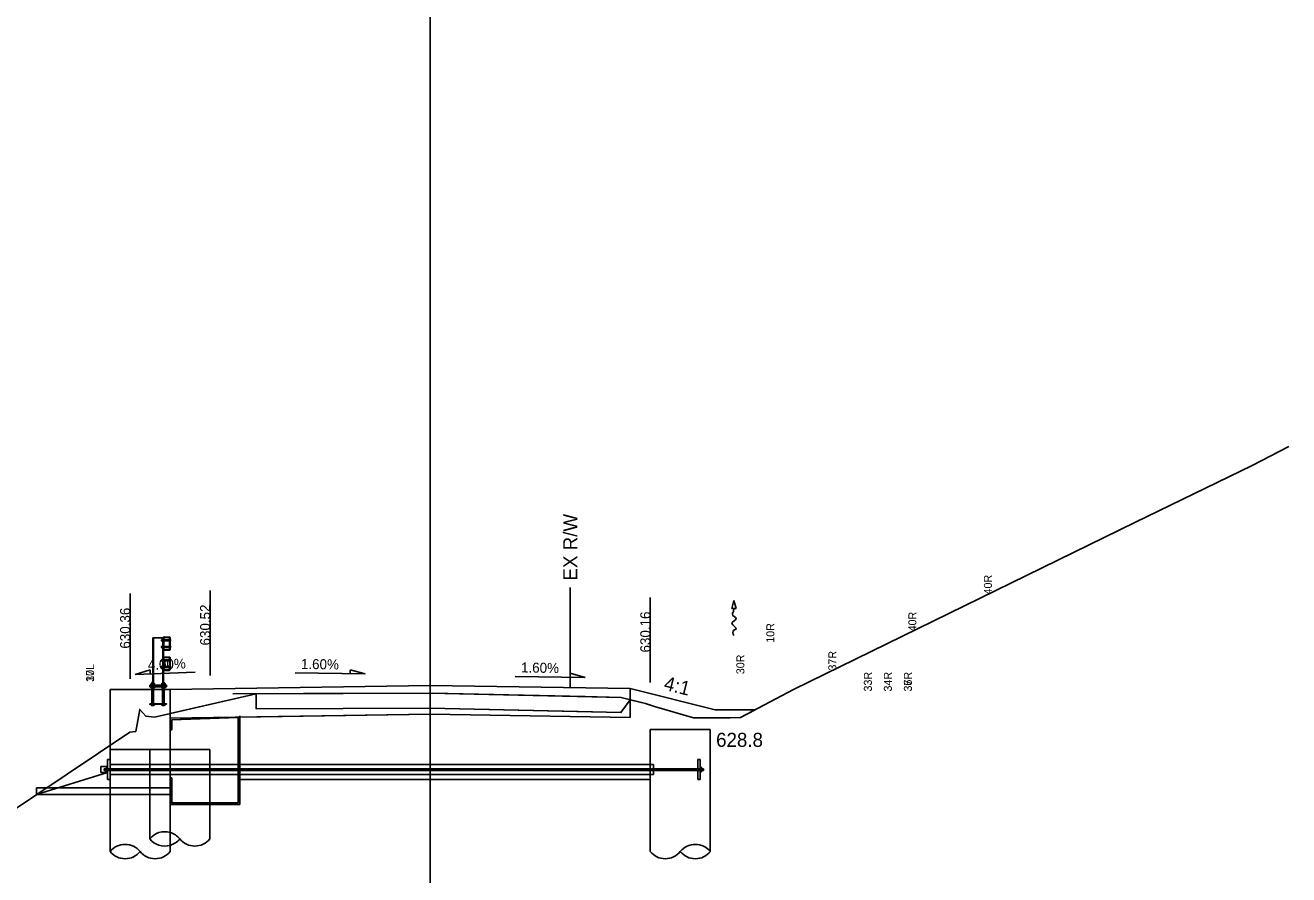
# Model space of a CAD drawing. Extents: x 1866342 to 1870084, y 421982 to 426629.
# Drawn here: x 1866447.9 to 1866511, y 425518.2 to 425560.6 of the extents above; entities that cross this region are included whole.
import ezdxf

# ---------------------------------------------------------------- set-up
doc = ezdxf.new("R2010")
doc.units = 0
for name, color, linetype in [('BR_P_Det_Object', 7, 'Continuous'), ('BR_P_Drain_Object', 7, 'Continuous'), ('BR_P_Gen_Hatch', 7, 'Continuous'), ('BR_P_Gen_Porous_Backfill', 7, 'Continuous'), ('BR_P_Sub_Deep_Hidden', 7, 'Continuous'), ('BR_P_Sub_Deep_Object', 7, 'Continuous'), ('BR_P_Sub_Object', 7, 'Continuous'), ('DR_P_Flow_Arrow', 7, 'Continuous'), ('GK_Cells', 7, 'Continuous'), ('RW_X_Fee_RW', 7, 'Continuous'), ('ST_Details', 7, 'Continuous'), ('XS_P_Annotation', 7, 'Continuous'), ('XS_P_Earthwork_Shapes', 7, 'Continuous'), ('XS_P_Finished_Grade', 7, 'Continuous'), ('XS_P_Pavt_Surface', 7, 'Continuous'), ('XS_P_Subgrade', 7, 'Continuous'), ('XS_P_Text_Info', 7, 'Continuous'), ('XS_P_Text_MarkedPoint', 7, 'Continuous'), ('XS_X_Ground_Line', 7, 'Continuous')]:
    doc.layers.add(name, color=color, linetype=linetype)

msp = doc.modelspace()

# ---------------------------------------------------------------- linework, layer by layer
at = {"layer": 'BR_P_Det_Object'}
for p, q in [((1866451.994, 425522.946), (1866451.994, 425523.946)), ((1866451.994, 425523.946), (1866452.119, 425523.946)), ((1866452.119, 425523.946), (1866452.119, 425522.946)), ((1866481.494, 425523.946), (1866481.494, 425522.946)), ((1866481.619, 425523.946), (1866481.494, 425523.946)), ((1866481.619, 425522.946), (1866481.619, 425523.946)), ((1866451.66, 425523.296), (1866451.66, 425523.594)), ((1866451.66, 425523.594), (1866451.994, 425523.594)), ((1866451.994, 425523.296), (1866451.66, 425523.296)), ((1866451.827, 425523.488), (1866481.785, 425523.488)), ((1866451.827, 425523.405), (1866451.827, 425523.488)), ((1866451.827, 425523.405), (1866481.785, 425523.405)), ((1866451.994, 425523.541), (1866451.93, 425523.541)), ((1866451.93, 425523.352), (1866451.93, 425523.541)), ((1866451.994, 425523.352), (1866451.93, 425523.352)), ((1866452.119, 425523.696), (1866455.119, 425523.696)), ((1866452.119, 425523.196), (1866455.119, 425523.196)), ((1866481.619, 425523.561), (1866481.682, 425523.561)), ((1866481.619, 425523.331), (1866481.682, 425523.331)), ((1866481.682, 425523.331), (1866481.682, 425523.561)), ((1866481.785, 425523.405), (1866481.785, 425523.488)), ((1866452.119, 425522.946), (1866451.994, 425522.946)), ((1866481.619, 425522.946), (1866481.494, 425522.946))]:
    msp.add_line(p, q, dxfattribs=at)
at = {"layer": 'BR_P_Drain_Object'}
for p, q in [((1866455.119, 425523.696), (1866479.285, 425523.696)), ((1866455.119, 425523.196), (1866479.285, 425523.196)), ((1866479.285, 425523.696), (1866479.285, 425523.196)), ((1866448.434, 425522.53), (1866455.119, 425522.53)), ((1866448.434, 425522.196), (1866448.434, 425522.53)), ((1866448.434, 425522.196), (1866455.119, 425522.196))]:
    msp.add_line(p, q, dxfattribs=at)
at = {"layer": 'BR_P_Gen_Hatch'}
msp.add_lwpolyline([(1866455.119, 425525.429), (1866455.202, 425525.429), (1866455.202, 425525.929), (1866458.519, 425526.052), (1866458.519, 425521.78), (1866455.202, 425521.78), (1866455.202, 425523.03), (1866455.119, 425523.03)], close=True, dxfattribs=at)
at = {"layer": 'BR_P_Gen_Porous_Backfill'}
for p, q in [((1866455.202, 425525.929), (1866458.119, 425526.046)), ((1866455.202, 425525.429), (1866455.202, 425525.929)), ((1866458.519, 425526.052), (1866458.119, 425526.046)), ((1866458.519, 425521.78), (1866458.519, 425526.052)), ((1866455.202, 425525.429), (1866455.119, 425525.429)), ((1866455.202, 425523.03), (1866455.119, 425523.03)), ((1866455.202, 425521.78), (1866455.202, 425523.03)), ((1866455.202, 425521.78), (1866458.519, 425521.78))]:
    msp.add_line(p, q, dxfattribs=at)
at = {"layer": 'BR_P_Sub_Deep_Hidden'}
msp.add_line((1866457.103, 425524.446), (1866455.119, 425524.446), dxfattribs=at)
for points in [[(1866454.103, 425519.983), (1866454.103, 425524.446)], [(1866457.103, 425521.696), (1866457.103, 425524.446)]]:
    msp.add_lwpolyline(points, dxfattribs=at)
for centre, major_axis, start_param, end_param in [((1866454.853, 425519.38), (0.908, 0.32), 0.952163, 2.125879), ((1866454.853, 425520.586), (0.908, -0.32), 4.157306, 5.331022)]:
    msp.add_ellipse(centre, major_axis=major_axis, ratio=0.999997, start_param=start_param, end_param=end_param, dxfattribs=at)
at = {"layer": 'BR_P_Sub_Deep_Object'}
msp.add_line((1866479.119, 425525.446), (1866482.119, 425525.446), dxfattribs=at)
for points in [[(1866479.119, 425519.35), (1866479.119, 425525.446)], [(1866482.119, 425519.35), (1866482.119, 425525.446)], [(1866452.119, 425519.35), (1866452.119, 425524.446)], [(1866455.119, 425519.35), (1866455.119, 425524.446)], [(1866457.103, 425519.983), (1866457.103, 425521.696)]]:
    msp.add_lwpolyline(points, dxfattribs=at)
for centre, major_axis, start_param, end_param in [((1866454.853, 425519.38), (0.908, 0.32), 0.338571, 0.952163), ((1866452.869, 425518.747), (0.908, 0.32), 0.338571, 2.125879), ((1866454.853, 425520.586), (0.908, -0.32), 5.331022, 5.944615), ((1866456.353, 425520.586), (0.908, 0.32), 3.480163, 5.267472), ((1866481.369, 425518.747), (-0.908, 0.32), 4.157306, 5.944615), ((1866452.869, 425519.953), (0.908, -0.32), 4.157306, 5.944615), ((1866454.369, 425519.953), (0.908, 0.32), 3.480163, 5.267472), ((1866479.869, 425519.953), (-0.908, 0.32), 1.015713, 2.803022), ((1866481.369, 425519.953), (-0.908, -0.32), 0.33857, 2.125879)]:
    msp.add_ellipse(centre, major_axis=major_axis, ratio=0.999997, start_param=start_param, end_param=end_param, dxfattribs=at)
at = {"layer": 'BR_P_Sub_Object'}
for p, q in [((1866455.119, 425527.446), (1866452.119, 425527.446)), ((1866452.119, 425527.446), (1866452.119, 425524.446)), ((1866455.119, 425524.446), (1866455.119, 425527.446))]:
    msp.add_line(p, q, dxfattribs=at)
msp.add_lwpolyline([(1866455.119, 425524.446), (1866452.119, 425524.446)], dxfattribs=at)
at = {"layer": 'DR_P_Flow_Arrow'}
for p, q in [((1866483.188, 425531.488), (1866483.295, 425531.888)), ((1866483.402, 425531.488), (1866483.188, 425531.488)), ((1866483.295, 425531.888), (1866483.402, 425531.488))]:
    msp.add_line(p, q, dxfattribs=at)
msp.add_spline([(1866483.294, 425531.489), (1866483.294, 425531.473), (1866483.256, 425531.308), (1866483.22, 425531.204), (1866483.404, 425530.992), (1866483.198, 425530.75), (1866483.404, 425530.47), (1866483.292, 425530.413), (1866483.295, 425530.138)], degree=3, dxfattribs=at)
at = {"layer": 'GK_Cells'}
msp.add_line((1866468.119, 425490.634), (1866468.119, 425637.486), dxfattribs=at)
at = {"layer": 'RW_X_Fee_RW'}
msp.add_line((1866475.119, 425527.542), (1866475.119, 425532.542), dxfattribs=at)
at = {"layer": 'ST_Details'}
for p, q in [((1866454.254, 425530.03), (1866454.254, 425527.811)), ((1866454.785, 425530.03), (1866454.254, 425530.03)), ((1866454.292, 425530.03), (1866454.292, 425527.805)), ((1866454.701, 425529.931), (1866454.685, 425529.931)), ((1866454.685, 425529.931), (1866454.685, 425529.879)), ((1866454.701, 425529.879), (1866454.685, 425529.879)), ((1866454.701, 425529.597), (1866454.685, 425529.597)), ((1866454.685, 425529.597), (1866454.685, 425529.545)), ((1866454.701, 425529.545), (1866454.685, 425529.545)), ((1866454.701, 425529.938), (1866454.701, 425529.871)), ((1866454.701, 425529.605), (1866454.701, 425529.538)), ((1866454.71, 425529.883), (1866454.747, 425529.883)), ((1866454.71, 425529.549), (1866454.747, 425529.549)), ((1866454.747, 425529.949), (1866454.711, 425529.949)), ((1866454.711, 425529.927), (1866454.747, 425529.927)), ((1866454.711, 425529.86), (1866454.747, 425529.86)), ((1866454.747, 425529.616), (1866454.711, 425529.616)), ((1866454.711, 425529.593), (1866454.747, 425529.593)), ((1866454.711, 425529.527), (1866454.747, 425529.527)), ((1866454.747, 425530.03), (1866454.747, 425527.805)), ((1866454.747, 425529.86), (1866454.747, 425529.949)), ((1866454.747, 425529.527), (1866454.747, 425529.616)), ((1866454.785, 425530.03), (1866454.785, 425527.811)), ((1866454.785, 425530.019), (1866454.785, 425529.457)), ((1866454.811, 425530.019), (1866454.811, 425529.457)), ((1866454.811, 425529.931), (1866455.093, 425529.931)), ((1866454.811, 425529.879), (1866455.093, 425529.879)), ((1866454.811, 425529.597), (1866455.093, 425529.597)), ((1866454.811, 425529.545), (1866455.093, 425529.545)), ((1866455.067, 425530.071), (1866454.837, 425530.071)), ((1866455.067, 425530.045), (1866454.837, 425530.045)), ((1866455.093, 425529.457), (1866455.093, 425530.019)), ((1866455.119, 425529.457), (1866455.119, 425530.019)), ((1866454.701, 425528.931), (1866454.685, 425528.931)), ((1866454.685, 425528.931), (1866454.685, 425528.879)), ((1866454.701, 425528.879), (1866454.685, 425528.879)), ((1866454.701, 425528.938), (1866454.701, 425528.871)), ((1866454.71, 425528.883), (1866454.747, 425528.883)), ((1866454.747, 425528.949), (1866454.711, 425528.949)), ((1866454.711, 425528.927), (1866454.747, 425528.927)), ((1866454.711, 425528.86), (1866454.747, 425528.86)), ((1866454.747, 425528.86), (1866454.747, 425528.949)), ((1866454.785, 425529.04), (1866454.785, 425528.436)), ((1866454.811, 425529.019), (1866454.811, 425528.457)), ((1866454.811, 425528.931), (1866455.093, 425528.931)), ((1866454.811, 425528.879), (1866455.093, 425528.879)), ((1866455.087, 425529.071), (1866454.817, 425529.071)), ((1866454.837, 425529.431), (1866455.067, 425529.431)), ((1866454.837, 425529.405), (1866455.067, 425529.405)), ((1866455.067, 425529.045), (1866454.837, 425529.045)), ((1866455.093, 425528.457), (1866455.093, 425529.019)), ((1866455.119, 425528.436), (1866455.119, 425529.04)), ((1866454.701, 425528.597), (1866454.685, 425528.597)), ((1866454.685, 425528.597), (1866454.685, 425528.545)), ((1866454.701, 425528.545), (1866454.685, 425528.545)), ((1866454.701, 425528.605), (1866454.701, 425528.538)), ((1866454.71, 425528.549), (1866454.747, 425528.549)), ((1866454.747, 425528.616), (1866454.711, 425528.616)), ((1866454.711, 425528.593), (1866454.747, 425528.593)), ((1866454.711, 425528.527), (1866454.747, 425528.527)), ((1866454.747, 425528.527), (1866454.747, 425528.616)), ((1866454.811, 425528.597), (1866455.093, 425528.597)), ((1866454.811, 425528.545), (1866455.093, 425528.545)), ((1866454.817, 425528.405), (1866455.087, 425528.405)), ((1866454.837, 425528.431), (1866455.067, 425528.431)), ((1866454.171, 425527.68), (1866454.337, 425527.68)), ((1866454.171, 425527.665), (1866454.171, 425527.68)), ((1866454.337, 425527.665), (1866454.171, 425527.665)), ((1866454.176, 425527.746), (1866454.176, 425527.68)), ((1866454.332, 425527.68), (1866454.176, 425527.68)), ((1866454.195, 425527.762), (1866454.312, 425527.762)), ((1866454.212, 425527.801), (1866454.223, 425527.811)), ((1866454.212, 425527.801), (1866454.296, 425527.801)), ((1866454.212, 425527.801), (1866454.212, 425527.762)), ((1866454.212, 425527.79), (1866454.296, 425527.79)), ((1866454.212, 425527.78), (1866454.296, 425527.78)), ((1866454.212, 425527.77), (1866454.296, 425527.77)), ((1866454.212, 425527.665), (1866454.212, 425527.582)), ((1866454.215, 425527.746), (1866454.215, 425527.68)), ((1866454.285, 425527.811), (1866454.223, 425527.811)), ((1866454.285, 425527.811), (1866454.296, 425527.801)), ((1866454.293, 425527.746), (1866454.293, 425527.68)), ((1866454.296, 425527.762), (1866454.296, 425527.801)), ((1866454.296, 425527.582), (1866454.296, 425527.665)), ((1866454.332, 425527.746), (1866454.332, 425527.68)), ((1866454.337, 425527.68), (1866454.337, 425527.665)), ((1866454.868, 425527.68), (1866454.702, 425527.68)), ((1866454.702, 425527.68), (1866454.702, 425527.665)), ((1866454.702, 425527.665), (1866454.868, 425527.665)), ((1866454.707, 425527.746), (1866454.707, 425527.68)), ((1866454.707, 425527.68), (1866454.863, 425527.68)), ((1866454.844, 425527.762), (1866454.726, 425527.762)), ((1866454.754, 425527.811), (1866454.743, 425527.801)), ((1866454.827, 425527.801), (1866454.743, 425527.801)), ((1866454.743, 425527.762), (1866454.743, 425527.801)), ((1866454.827, 425527.79), (1866454.743, 425527.79)), ((1866454.827, 425527.78), (1866454.743, 425527.78)), ((1866454.827, 425527.77), (1866454.743, 425527.77)), ((1866454.743, 425527.582), (1866454.743, 425527.665)), ((1866454.746, 425527.746), (1866454.746, 425527.68)), ((1866454.754, 425527.811), (1866454.816, 425527.811)), ((1866454.827, 425527.801), (1866454.816, 425527.811)), ((1866454.824, 425527.746), (1866454.824, 425527.68)), ((1866454.827, 425527.801), (1866454.827, 425527.762)), ((1866454.827, 425527.665), (1866454.827, 425527.582)), ((1866454.863, 425527.746), (1866454.863, 425527.68)), ((1866454.868, 425527.665), (1866454.868, 425527.68)), ((1866454.171, 425527.582), (1866454.337, 425527.582)), ((1866454.171, 425527.567), (1866454.171, 425527.582)), ((1866454.337, 425527.567), (1866454.171, 425527.567)), ((1866454.176, 425527.537), (1866454.176, 425527.567)), ((1866454.195, 425527.522), (1866454.312, 425527.522)), ((1866454.212, 425527.457), (1866454.212, 425527.522)), ((1866454.212, 425527.457), (1866454.212, 425526.738)), ((1866454.215, 425527.537), (1866454.215, 425527.567)), ((1866454.293, 425527.537), (1866454.293, 425527.567)), ((1866454.296, 425527.457), (1866454.296, 425527.522)), ((1866454.296, 425526.738), (1866454.296, 425527.457)), ((1866454.332, 425527.537), (1866454.332, 425527.567)), ((1866454.337, 425527.582), (1866454.337, 425527.567)), ((1866454.702, 425527.582), (1866454.868, 425527.582)), ((1866454.702, 425527.567), (1866454.702, 425527.582)), ((1866454.868, 425527.567), (1866454.702, 425527.567)), ((1866454.707, 425527.537), (1866454.707, 425527.567)), ((1866454.726, 425527.522), (1866454.844, 425527.522)), ((1866454.743, 425527.457), (1866454.743, 425527.522)), ((1866454.743, 425526.738), (1866454.743, 425527.457)), ((1866454.746, 425527.537), (1866454.746, 425527.567)), ((1866454.824, 425527.537), (1866454.824, 425527.567)), ((1866454.827, 425527.457), (1866454.827, 425527.522)), ((1866454.827, 425527.457), (1866454.827, 425526.738)), ((1866454.863, 425527.537), (1866454.863, 425527.567)), ((1866454.868, 425527.582), (1866454.868, 425527.567)), ((1866454.176, 425526.672), (1866454.176, 425526.707)), ((1866454.195, 425526.656), (1866454.312, 425526.656)), ((1866454.215, 425526.672), (1866454.215, 425526.707)), ((1866454.293, 425526.672), (1866454.293, 425526.707)), ((1866454.332, 425526.672), (1866454.332, 425526.707)), ((1866454.707, 425526.672), (1866454.707, 425526.707)), ((1866454.844, 425526.656), (1866454.726, 425526.656)), ((1866454.746, 425526.672), (1866454.746, 425526.707)), ((1866454.824, 425526.672), (1866454.824, 425526.707)), ((1866454.863, 425526.672), (1866454.863, 425526.707))]:
    msp.add_line(p, q, dxfattribs=at)
for points in [[(1866454.103, 425527.665), (1866454.936, 425527.665), (1866454.936, 425527.582), (1866454.103, 425527.582)], [(1866454.103, 425526.738), (1866454.936, 425526.738), (1866454.936, 425526.707), (1866454.103, 425526.707)]]:
    msp.add_lwpolyline(points, close=True, dxfattribs=at)
for centre, radius, start, end in [((1866454.837, 425530.019), 0.0521, 90, 180), ((1866454.837, 425530.019), 0.026, 90, 180), ((1866455.067, 425530.019), 0.0521, 0, 90), ((1866455.067, 425530.019), 0.026, 0, 90), ((1866455.091, 425529.905), 0.0558, 300, 60), ((1866455.091, 425529.571), 0.0558, 300, 60), ((1866454.837, 425529.457), 0.0521, 180, 270), ((1866454.817, 425529.04), 0.0312, 90, 180), ((1866454.837, 425529.457), 0.026, 180, 270), ((1866454.837, 425529.019), 0.026, 90, 180), ((1866455.067, 425529.457), 0.0521, 270, 0), ((1866455.067, 425529.457), 0.026, 270, 0), ((1866455.067, 425529.019), 0.026, 0, 90), ((1866455.087, 425529.04), 0.0312, 0, 90), ((1866455.091, 425528.905), 0.0558, 300, 60), ((1866454.817, 425528.436), 0.0312, 180, 270), ((1866454.837, 425528.457), 0.026, 180, 270), ((1866455.067, 425528.457), 0.026, 270, 0), ((1866455.087, 425528.436), 0.0312, 270, 0), ((1866455.091, 425528.571), 0.0558, 300, 60)]:
    msp.add_arc(centre, radius, start, end, dxfattribs=at)
for centre, major_axis, ratio, start_param, end_param in [((1866454.711, 425529.938), (0, -0.0111), 0.939759, 3.141593, 6.283185), ((1866454.711, 425529.905), (0, -0.0222), 0.469173, 3.141593, 6.283185), ((1866454.711, 425529.871), (0, 0.0111), 0.939759, 0, 3.141593), ((1866454.711, 425529.605), (0, -0.0111), 0.939759, 3.141593, 6.283185), ((1866454.711, 425529.571), (0, -0.0222), 0.469173, 3.141593, 6.283185), ((1866454.711, 425529.538), (0, 0.0111), 0.939759, 0, 3.141593), ((1866454.711, 425528.938), (0, -0.0111), 0.939759, 3.141593, 6.283185), ((1866454.711, 425528.905), (0, -0.0222), 0.469173, 3.141593, 6.283185), ((1866454.711, 425528.871), (0, 0.0111), 0.939759, 0, 3.141593), ((1866454.711, 425528.605), (0, -0.0111), 0.939759, 3.141593, 6.283185), ((1866454.711, 425528.571), (0, -0.0222), 0.469173, 3.141593, 6.283185), ((1866454.711, 425528.538), (0, 0.0111), 0.939759, 0, 3.141593), ((1866454.195, 425527.746), (0.0195, 0), 0.798056, 0, 3.141593), ((1866454.254, 425527.746), (0.0391, 0), 0.399304, 0, 3.141593), ((1866454.312, 425527.746), (0.0195, 0), 0.798056, 0, 3.141593), ((1866454.726, 425527.746), (-0.0195, 0), 0.798056, 3.141593, 6.283185), ((1866454.785, 425527.746), (-0.0391, 0), 0.399304, 3.141593, 6.283185), ((1866454.844, 425527.746), (-0.0195, 0), 0.798056, 3.141593, 6.283185), ((1866454.195, 425527.537), (0.0195, 0), 0.798056, 3.141593, 6.283185), ((1866454.254, 425527.537), (0.0391, 0), 0.399304, 3.141593, 6.283185), ((1866454.312, 425527.537), (0.0195, 0), 0.798056, 3.141593, 6.283185), ((1866454.726, 425527.537), (0.0195, 0), 0.798056, 3.141593, 6.283185), ((1866454.785, 425527.537), (0.0391, 0), 0.399304, 3.141593, 6.283185), ((1866454.844, 425527.537), (0.0195, 0), 0.798056, 3.141593, 6.283185), ((1866454.195, 425526.672), (0.0195, 0), 0.798056, 3.141593, 6.283185), ((1866454.254, 425526.672), (0.0391, 0), 0.399304, 3.141593, 6.283185), ((1866454.312, 425526.672), (0.0195, 0), 0.798056, 3.141593, 6.283185), ((1866454.726, 425526.672), (-0.0195, 0), 0.798056, 0, 3.141593), ((1866454.785, 425526.672), (-0.0391, 0), 0.399304, 0, 3.141593), ((1866454.844, 425526.672), (-0.0195, 0), 0.798056, 0, 3.141593)]:
    msp.add_ellipse(centre, major_axis=major_axis, ratio=ratio, start_param=start_param, end_param=end_param, dxfattribs=at)
at = {"layer": 'XS_P_Annotation'}
for q in [(1866455.119, 425527.446), (1866478.119, 425527.494)]:
    msp.add_line((1866468.119, 425527.654), q, dxfattribs=at)
at = {"layer": 'XS_P_Earthwork_Shapes'}
for p, q in [((1866482.366, 425526.433), (1866478.119, 425527.494)), ((1866478.119, 425527.494), (1866478.119, 425526.934)), ((1866478.119, 425526.057), (1866478.119, 425526.934)), ((1866478.119, 425526.934), (1866478.879, 425526.743)), ((1866484.366, 425526.433), (1866482.366, 425526.433)), ((1866455.119, 425526.245), (1866455.119, 425526.009)), ((1866468.119, 425526.217), (1866478.119, 425526.057))]:
    msp.add_line(p, q, dxfattribs=at)
for points in [[(1866478.119, 425526.934), (1866477.648, 425526.298), (1866475.508, 425526.347), (1866468.119, 425526.517), (1866459.426, 425526.479), (1866459.422, 425527.229), (1866455.119, 425526.245)], [(1866459.422, 425527.229), (1866468.119, 425527.267), (1866477.666, 425527.048)], [(1866459.426, 425526.479), (1866468.112, 425526.517), (1866477.648, 425526.298)], [(1866478.879, 425526.743), (1866479.326, 425526.6), (1866481.28, 425526.037), (1866483.117, 425526.04), (1866483.635, 425526.045), (1866484.366, 425526.433)], [(1866455.119, 425526.009), (1866458.603, 425526.065), (1866468.119, 425526.217)]]:
    msp.add_lwpolyline(points, dxfattribs=at)
at = {"layer": 'XS_P_Finished_Grade'}
for p, q in [((1866478.119, 425527.494), (1866482.366, 425526.433)), ((1866482.366, 425526.433), (1866484.366, 425526.433)), ((1866451.994, 425523.294), (1866448.434, 425522.196))]:
    msp.add_line(p, q, dxfattribs=at)
at = {"layer": 'XS_P_Pavt_Surface'}
for p, q in [((1866458.254, 425527.224), (1866468.254, 425527.267)), ((1866468.254, 425527.267), (1866477.666, 425527.048))]:
    msp.add_line(p, q, dxfattribs=at)
at = {"layer": 'XS_P_Subgrade'}
for p, q in [((1866455.119, 425527.446), (1866455.119, 425526.009)), ((1866455.119, 425527.446), (1866455.119, 425526.009)), ((1866478.119, 425527.494), (1866478.119, 425526.057)), ((1866468.119, 425526.217), (1866455.119, 425526.009)), ((1866458.603, 425521.696), (1866458.603, 425526.129)), ((1866468.119, 425526.217), (1866478.119, 425526.057)), ((1866458.603, 425522.946), (1866479.119, 425522.946)), ((1866455.119, 425521.696), (1866458.603, 425521.696))]:
    msp.add_line(p, q, dxfattribs=at)
at = {"layer": 'XS_P_Text_Info'}
for p, q in [((1866453.119, 425527.989), (1866453.119, 425532.239)), ((1866457.119, 425528.149), (1866457.119, 425532.399)), ((1866479.119, 425527.797), (1866479.119, 425532.047)), ((1866454.119, 425528.429), (1866453.369, 425528.199)), ((1866456.369, 425528.319), (1866453.369, 425528.199)), ((1866454.119, 425528.229), (1866454.119, 425528.429)), ((1866461.369, 425528.281), (1866464.869, 425528.225)), ((1866464.119, 425528.437), (1866464.869, 425528.225)), ((1866464.119, 425528.237), (1866464.119, 425528.437)), ((1866475.119, 425528.261), (1866475.869, 425528.049)), ((1866475.119, 425528.061), (1866475.119, 425528.261)), ((1866472.369, 425528.105), (1866475.869, 425528.049))]:
    msp.add_line(p, q, dxfattribs=at)
at = {"layer": 'XS_X_Ground_Line'}
msp.add_line((1866452.119, 425527.446), (1866452.119, 425525.446), dxfattribs=at)
msp.add_lwpolyline([(1866445.3, 425520.104), (1866453.1, 425525.312), (1866453.4, 425525.35), (1866453.605, 425526.449), (1866453.899, 425526.109), (1866454.333, 425526.065), (1866459.422, 425527.229), (1866461.783, 425527.256), (1866468.254, 425527.267), (1866475.86, 425527.101), (1866477.666, 425527.048), (1866478.879, 425526.743), (1866479.326, 425526.6), (1866481.28, 425526.037), (1866483.117, 425526.04), (1866483.635, 425526.045), (1866486.281, 425527.448), (1866503.368, 425535.805), (1866509.207, 425538.633), (1866511.028, 425539.585)], dxfattribs=at)

# ---------------------------------------------------------------- texts
at = {"layer": 'RW_X_Fee_RW'}
msp.add_text('EX R/W', height=0.7, rotation=90, dxfattribs=at).set_placement((1866475.469, 425532.892))
at = {"layer": 'XS_P_Annotation'}
msp.add_text('4:1', height=0.7, rotation=345.96376, dxfattribs=at).set_placement((1866479.752, 425527.447))
msp.add_text('628.8', height=0.7, dxfattribs=at).set_placement((1866482.407, 425524.583))
at = {"layer": 'XS_P_Text_Info'}
for s, rotation, p in [('630.36', 90, (1866453.119, 425529.489)), ('630.52', 90, (1866457.119, 425529.649)), ('630.16', 90, (1866479.119, 425529.297)), ('4.00%', 2.29061, (1866454.013, 425528.426)), ('1.60%', 359.08335, (1866461.655, 425528.477)), ('1.60%', 359.08335, (1866472.655, 425528.301))]:
    msp.add_text(s, height=0.5, rotation=rotation, dxfattribs=at).set_placement(p)
at = {"layer": 'XS_P_Text_MarkedPoint'}
for s, p in [('40R', (1866496.192, 425532.197)), ('40R', (1866492.417, 425530.351)), ('10R', (1866485.319, 425529.783)), ('30R', (1866483.819, 425528.211)), ('37R', (1866488.417, 425528.395)), ('10L', (1866451.319, 425527.829)), ('37L', (1866451.319, 425527.829)), ('33R', (1866490.192, 425527.347)), ('34R', (1866491.192, 425527.347)), ('35R', (1866492.192, 425527.347)), ('36R', (1866492.192, 425527.347)), ('37R', (1866492.192, 425527.347))]:
    msp.add_text(s, height=0.4, rotation=90, dxfattribs=at).set_placement(p)

doc.saveas('drawing.dxf')
